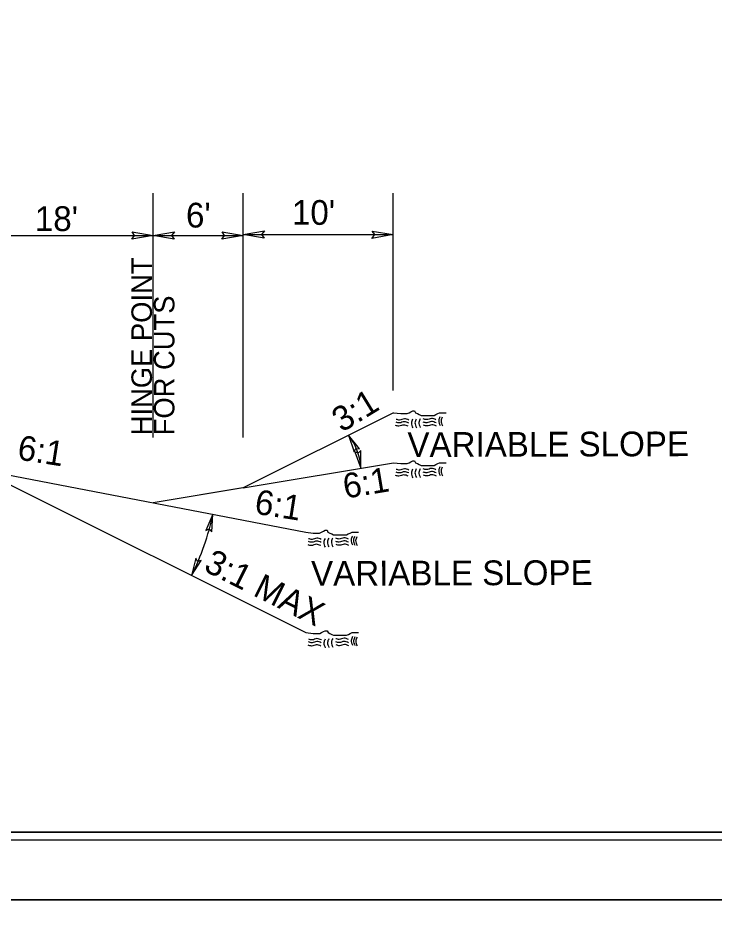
# Model space of a CAD drawing. Extents: x 2241081 to 2251104, y 658534 to 663427.
# Drawn here: x 2248675.9 to 2248908, y 659619.3 to 659923.1 of the extents above; entities that cross this region are included whole.
import ezdxf

# ---------------------------------------------------------------- set-up
doc = ezdxf.new("R2010")
doc.units = 0
for name, color, linetype in [('Old_Level_1', 7, 'Continuous'), ('Old_Level_2', 7, 'Continuous'), ('Prop Dimension', 7, 'Continuous'), ('Prop Dimension Text', 7, 'Continuous'), ('Prop PHM Text', 7, 'Continuous'), ('Sheet Cutting Line CELL', 7, 'Continuous'), ('Sheet Plan CELL', 7, 'Continuous'), ('Sheet Plot Border Inside CELL', 7, 'Continuous'), ('Sheet Plot Border Outside CELL', 7, 'Continuous'), ('Typical Hinge Slope Interstate CELL', 7, 'Continuous'), ('Typical Terminator CELL', 7, 'Continuous')]:
    doc.layers.add(name, color=color, linetype=linetype)

msp = doc.modelspace()

# ---------------------------------------------------------------- linework, layer by layer
at = {"layer": 'Old_Level_1'}
for p, q in [((2248800.89, 659791.62), (2248750.89, 659766.62)), ((2248662.87, 659772.79), (2248771.71, 659751.84)), ((2248750.89, 659766.62), (2248800.89, 659774.96)), ((2248750.89, 659766.62), (2248728.89, 659762.95))]:
    msp.add_line(p, q, dxfattribs=at)
for points in [[(2248800.89, 659791.62), (2248803.35, 659791.32), (2248803.97, 659791.32), (2248804.9, 659791.32), (2248805.51, 659791.32), (2248806.13, 659791.62), (2248806.74, 659791.93), (2248807.36, 659792.24), (2248807.98, 659792.24), (2248808.28, 659791.62), (2248808.9, 659791.32), (2248809.52, 659791.01), (2248810.13, 659790.7), (2248810.75, 659790.7), (2248811.37, 659790.7), (2248811.98, 659790.7), (2248812.6, 659790.7), (2248813.21, 659790.7), (2248813.83, 659790.7), (2248814.45, 659790.7), (2248815.06, 659791.01), (2248815.68, 659791.32), (2248816.29, 659791.62), (2248817.22, 659791.62), (2248817.84, 659791.62), (2248818.45, 659791.62)], [(2248800.89, 659774.96), (2248803.35, 659774.65), (2248803.97, 659774.65), (2248804.9, 659774.65), (2248805.51, 659774.65), (2248806.13, 659774.96), (2248806.74, 659775.27), (2248807.36, 659775.58), (2248807.98, 659775.58), (2248808.28, 659774.96), (2248808.9, 659774.65), (2248809.52, 659774.34), (2248810.13, 659774.03), (2248810.75, 659774.03), (2248811.37, 659774.03), (2248811.98, 659774.03), (2248812.6, 659774.03), (2248813.21, 659774.03), (2248813.83, 659774.03), (2248814.45, 659774.03), (2248815.06, 659774.34), (2248815.68, 659774.65), (2248816.29, 659774.96), (2248817.22, 659774.96), (2248817.84, 659774.96), (2248818.45, 659774.96)], [(2248771.71, 659751.84), (2248774.17, 659751.53), (2248774.79, 659751.53), (2248775.72, 659751.53), (2248776.33, 659751.53), (2248776.95, 659751.84), (2248777.56, 659752.15), (2248778.18, 659752.46), (2248778.8, 659752.46), (2248779.11, 659751.84), (2248779.72, 659751.53), (2248780.34, 659751.22), (2248780.95, 659750.92), (2248781.57, 659750.92), (2248782.19, 659750.92), (2248782.8, 659750.92), (2248783.42, 659750.92), (2248784.03, 659750.92), (2248784.65, 659750.92), (2248785.27, 659750.92), (2248785.88, 659751.22), (2248786.5, 659751.53), (2248787.12, 659751.84), (2248788.04, 659751.84), (2248788.66, 659751.84), (2248789.27, 659751.84)], [(2248771.75, 659718.35), (2248774.21, 659718.04), (2248774.83, 659718.04), (2248775.75, 659718.04), (2248776.37, 659718.04), (2248776.99, 659718.35), (2248777.6, 659718.66), (2248778.22, 659718.97), (2248778.83, 659718.97), (2248779.14, 659718.35), (2248779.76, 659718.04), (2248780.38, 659717.74), (2248780.99, 659717.43), (2248781.61, 659717.43), (2248782.22, 659717.43), (2248782.84, 659717.43), (2248783.46, 659717.43), (2248784.07, 659717.43), (2248784.69, 659717.43), (2248785.31, 659717.43), (2248785.92, 659717.74), (2248786.54, 659718.04), (2248787.15, 659718.35), (2248788.08, 659718.35), (2248788.69, 659718.35), (2248789.31, 659718.35)]]:
    msp.add_lwpolyline(points, dxfattribs=at)
for points in [[(2248806.02, 659788.2), (2248804.51, 659788.64), (2248802.93, 659788.23), (2248801.78, 659788.48)], [(2248806.02, 659788.2), (2248804.51, 659788.64), (2248802.93, 659788.23), (2248801.78, 659788.48)], [(2248806.06, 659789.15), (2248804.55, 659789.58), (2248802.97, 659789.17), (2248801.82, 659789.42)], [(2248806.06, 659789.15), (2248804.55, 659789.58), (2248802.97, 659789.17), (2248801.82, 659789.42)], [(2248807.31, 659789.43), (2248806.88, 659788.19), (2248807.34, 659786.55)], [(2248807.31, 659789.43), (2248806.88, 659788.19), (2248807.34, 659786.55)], [(2248808.52, 659789.54), (2248808.1, 659788.3), (2248808.55, 659786.65)], [(2248808.52, 659789.54), (2248808.1, 659788.3), (2248808.55, 659786.65)], [(2248809.83, 659789.64), (2248809.41, 659788.4), (2248809.86, 659786.76)], [(2248809.83, 659789.64), (2248809.41, 659788.4), (2248809.86, 659786.76)], [(2248815.09, 659789.29), (2248813.59, 659789.72), (2248811.99, 659789.32), (2248810.85, 659789.57)], [(2248815.09, 659789.29), (2248813.59, 659789.72), (2248811.99, 659789.32), (2248810.85, 659789.57)], [(2248815.1, 659788.24), (2248813.59, 659788.67), (2248812.01, 659788.26), (2248810.86, 659788.52)], [(2248815.1, 659788.24), (2248813.59, 659788.67), (2248812.01, 659788.26), (2248810.86, 659788.52)], [(2248816.42, 659790.26), (2248815.99, 659789.01), (2248816.45, 659787.37)], [(2248816.42, 659790.26), (2248815.99, 659789.01), (2248816.45, 659787.37)], [(2248817.2, 659790.18), (2248816.78, 659788.93), (2248817.24, 659787.28)], [(2248817.2, 659790.18), (2248816.78, 659788.93), (2248817.24, 659787.28)], [(2248805.87, 659787.11), (2248804.37, 659787.54), (2248802.77, 659787.14), (2248801.63, 659787.39)], [(2248805.87, 659787.11), (2248804.37, 659787.54), (2248802.77, 659787.14), (2248801.63, 659787.39)], [(2248815.22, 659787.19), (2248813.71, 659787.61), (2248812.12, 659787.21), (2248810.97, 659787.47)], [(2248815.22, 659787.19), (2248813.71, 659787.61), (2248812.12, 659787.21), (2248810.97, 659787.47)], [(2248806.06, 659772.48), (2248804.55, 659772.91), (2248802.97, 659772.51), (2248801.82, 659772.76)], [(2248806.06, 659772.48), (2248804.55, 659772.91), (2248802.97, 659772.51), (2248801.82, 659772.76)], [(2248807.31, 659772.77), (2248806.88, 659771.52), (2248807.34, 659769.88)], [(2248807.31, 659772.77), (2248806.88, 659771.52), (2248807.34, 659769.88)], [(2248808.52, 659772.88), (2248808.1, 659771.63), (2248808.55, 659769.99)], [(2248808.52, 659772.88), (2248808.1, 659771.63), (2248808.55, 659769.99)], [(2248809.83, 659772.98), (2248809.41, 659771.74), (2248809.86, 659770.09)], [(2248809.83, 659772.98), (2248809.41, 659771.74), (2248809.86, 659770.09)], [(2248815.09, 659772.62), (2248813.59, 659773.06), (2248811.99, 659772.65), (2248810.85, 659772.91)], [(2248815.09, 659772.62), (2248813.59, 659773.06), (2248811.99, 659772.65), (2248810.85, 659772.91)], [(2248816.42, 659773.59), (2248815.99, 659772.35), (2248816.45, 659770.71)], [(2248816.42, 659773.59), (2248815.99, 659772.35), (2248816.45, 659770.71)], [(2248817.2, 659773.51), (2248816.78, 659772.27), (2248817.24, 659770.62)], [(2248817.2, 659773.51), (2248816.78, 659772.27), (2248817.24, 659770.62)], [(2248805.87, 659770.45), (2248804.37, 659770.88), (2248802.77, 659770.47), (2248801.63, 659770.73)], [(2248805.87, 659770.45), (2248804.37, 659770.88), (2248802.77, 659770.47), (2248801.63, 659770.73)], [(2248806.02, 659771.54), (2248804.51, 659771.97), (2248802.93, 659771.56), (2248801.78, 659771.82)], [(2248806.02, 659771.54), (2248804.51, 659771.97), (2248802.93, 659771.56), (2248801.78, 659771.82)], [(2248815.1, 659771.58), (2248813.59, 659772), (2248812.01, 659771.6), (2248810.86, 659771.86)], [(2248815.1, 659771.58), (2248813.59, 659772), (2248812.01, 659771.6), (2248810.86, 659771.86)], [(2248815.22, 659770.52), (2248813.71, 659770.95), (2248812.12, 659770.55), (2248810.97, 659770.8)], [(2248815.22, 659770.52), (2248813.71, 659770.95), (2248812.12, 659770.55), (2248810.97, 659770.8)]]:
    msp.add_spline(points, degree=3, dxfattribs=at)
at = {"layer": 'Old_Level_2'}
for points in [[(2248776.84, 659748.42), (2248775.34, 659748.86), (2248773.75, 659748.44), (2248772.6, 659748.7)], [(2248776.84, 659748.42), (2248775.34, 659748.86), (2248773.75, 659748.44), (2248772.6, 659748.7)], [(2248776.88, 659749.37), (2248775.38, 659749.79), (2248773.79, 659749.39), (2248772.64, 659749.64)], [(2248776.88, 659749.37), (2248775.38, 659749.79), (2248773.79, 659749.39), (2248772.64, 659749.64)], [(2248778.13, 659749.65), (2248777.7, 659748.41), (2248778.16, 659746.76)], [(2248778.13, 659749.65), (2248777.7, 659748.41), (2248778.16, 659746.76)], [(2248779.34, 659749.76), (2248778.92, 659748.52), (2248779.37, 659746.87)], [(2248779.34, 659749.76), (2248778.92, 659748.52), (2248779.37, 659746.87)], [(2248780.65, 659749.86), (2248780.23, 659748.62), (2248780.68, 659746.97)], [(2248780.65, 659749.86), (2248780.23, 659748.62), (2248780.68, 659746.97)], [(2248785.91, 659749.51), (2248784.41, 659749.94), (2248782.82, 659749.53), (2248781.67, 659749.79)], [(2248785.91, 659749.51), (2248784.41, 659749.94), (2248782.82, 659749.53), (2248781.67, 659749.79)], [(2248785.92, 659748.46), (2248784.41, 659748.89), (2248782.83, 659748.48), (2248781.68, 659748.74)], [(2248785.92, 659748.46), (2248784.41, 659748.89), (2248782.83, 659748.48), (2248781.68, 659748.74)], [(2248787.24, 659750.48), (2248786.81, 659749.23), (2248787.27, 659747.59)], [(2248787.24, 659750.48), (2248786.81, 659749.23), (2248787.27, 659747.59)], [(2248788.02, 659750.39), (2248787.6, 659749.15), (2248788.06, 659747.5)], [(2248788.02, 659750.39), (2248787.6, 659749.15), (2248788.06, 659747.5)], [(2248788.75, 659750.25), (2248788.33, 659749.01), (2248788.78, 659747.36)], [(2248788.75, 659750.25), (2248788.33, 659749.01), (2248788.78, 659747.36)], [(2248776.69, 659747.33), (2248775.19, 659747.76), (2248773.59, 659747.35), (2248772.45, 659747.61)], [(2248786.04, 659747.4), (2248784.53, 659747.83), (2248782.94, 659747.43), (2248781.79, 659747.69)], [(2248786.04, 659747.4), (2248784.53, 659747.83), (2248782.94, 659747.43), (2248781.79, 659747.69)], [(2248776.88, 659714.93), (2248775.37, 659715.37), (2248773.79, 659714.96), (2248772.64, 659715.21)], [(2248776.88, 659714.93), (2248775.37, 659715.37), (2248773.79, 659714.96), (2248772.64, 659715.21)], [(2248776.92, 659715.88), (2248775.41, 659716.31), (2248773.83, 659715.9), (2248772.68, 659716.15)], [(2248776.92, 659715.88), (2248775.41, 659716.31), (2248773.83, 659715.9), (2248772.68, 659716.15)], [(2248778.16, 659716.16), (2248777.74, 659714.92), (2248778.2, 659713.28)], [(2248778.16, 659716.16), (2248777.74, 659714.92), (2248778.2, 659713.28)], [(2248779.38, 659716.27), (2248778.96, 659715.03), (2248779.41, 659713.38)], [(2248779.38, 659716.27), (2248778.96, 659715.03), (2248779.41, 659713.38)], [(2248780.69, 659716.37), (2248780.27, 659715.13), (2248780.72, 659713.48)], [(2248780.69, 659716.37), (2248780.27, 659715.13), (2248780.72, 659713.48)], [(2248785.95, 659716.02), (2248784.45, 659716.45), (2248782.85, 659716.05), (2248781.71, 659716.3)], [(2248785.95, 659716.02), (2248784.45, 659716.45), (2248782.85, 659716.05), (2248781.71, 659716.3)], [(2248785.96, 659714.97), (2248784.45, 659715.4), (2248782.87, 659714.99), (2248781.72, 659715.25)], [(2248785.96, 659714.97), (2248784.45, 659715.4), (2248782.87, 659714.99), (2248781.72, 659715.25)], [(2248787.28, 659716.99), (2248786.85, 659715.74), (2248787.31, 659714.1)], [(2248787.28, 659716.99), (2248786.85, 659715.74), (2248787.31, 659714.1)], [(2248788.06, 659716.91), (2248787.64, 659715.66), (2248788.09, 659714.01)], [(2248788.06, 659716.91), (2248787.64, 659715.66), (2248788.09, 659714.01)], [(2248788.79, 659716.76), (2248788.36, 659715.52), (2248788.82, 659713.87)], [(2248788.79, 659716.76), (2248788.36, 659715.52), (2248788.82, 659713.87)], [(2248776.73, 659713.84), (2248775.22, 659714.27), (2248773.63, 659713.86), (2248772.49, 659714.12)], [(2248786.07, 659713.91), (2248784.57, 659714.34), (2248782.97, 659713.94), (2248781.83, 659714.2)], [(2248786.07, 659713.91), (2248784.57, 659714.34), (2248782.97, 659713.94), (2248781.83, 659714.2)]]:
    msp.add_spline(points, degree=3, dxfattribs=at)
at = {"layer": 'Prop Dimension'}
for centre, radius, start, end in [((2248770.95, 659772.29), 19.12, 2.5693, 38.3323), ((2248661.39, 659774.2), 81.05, 333.0098, 348.3211)]:
    msp.add_arc(centre, radius, start, end, dxfattribs=at)
at = {"layer": 'Prop Dimension Text'}
for p, q in [((2248720.84, 659783.34), (2248720.84, 659864.81)), ((2248750.84, 659783.34), (2248750.84, 659864.81)), ((2248800.84, 659799.08), (2248800.84, 659864.81)), ((2248662.83, 659850.74), (2248720.84, 659850.74)), ((2248720.84, 659850.74), (2248750.84, 659850.74)), ((2248750.84, 659851.12), (2248750.84, 659851.12)), ((2248750.84, 659851), (2248800.84, 659851)), ((2248800.84, 659851.12), (2248800.84, 659851.12))]:
    msp.add_line(p, q, dxfattribs=at)
at = {"layer": 'Sheet Cutting Line CELL'}
for p, q in [((2247635.51, 659629.27), (2249319.01, 659629.26)), ((2249319.01, 659629.26), (2247635.51, 659629.27))]:
    msp.add_line(p, q, dxfattribs=at)
at = {"layer": 'Sheet Plan CELL'}
for points in [[(2247801.99, 659651.78), (2247801.97, 660701.75), (2249101.96, 660701.79), (2249101.97, 660551.73), (2249302.01, 660551.71), (2249302.01, 659651.78)], [(2249302.03, 660701.78), (2247801.99, 660701.78), (2247801.99, 659651.78), (2249302.01, 659651.78)]]:
    msp.add_lwpolyline(points, close=True, dxfattribs=at)
at = {"layer": 'Sheet Plot Border Inside CELL'}
msp.add_lwpolyline([(2247648.51, 659649.27), (2249314.49, 659649.28), (2249314.51, 660704.26), (2247648.51, 660704.27)], close=True, dxfattribs=at)
at = {"layer": 'Sheet Plot Border Outside CELL'}
for points in [[(2247635.51, 659629.27), (2249319.01, 659629.26), (2249319.01, 660724.26), (2247635.51, 660724.27)], [(2247635.5, 658534.27), (2249319, 658534.26), (2249319.01, 659629.26), (2247635.51, 659629.27)]]:
    msp.add_lwpolyline(points, close=True, dxfattribs=at)
at = {"layer": 'Typical Hinge Slope Interstate CELL'}
for p, q in [((2248662.87, 659772.79), (2248771.75, 659718.35)), ((2248751.39, 659766.7), (2248720.89, 659761.62))]:
    msp.add_line(p, q, dxfattribs=at)
at = {"layer": 'Typical Terminator CELL'}
for points in [[(2248713.81, 659851.95), (2248720.84, 659850.74), (2248713.77, 659849.49), (2248714.67, 659850.74)], [(2248727.87, 659849.53), (2248720.84, 659850.74), (2248727.91, 659851.99), (2248727.01, 659850.74)], [(2248743.81, 659851.95), (2248750.84, 659850.74), (2248743.77, 659849.49), (2248744.67, 659850.74)], [(2248757.87, 659849.79), (2248750.84, 659851), (2248757.91, 659852.25), (2248757.01, 659851)], [(2248793.81, 659852.21), (2248800.84, 659851), (2248793.77, 659849.75), (2248794.67, 659851)], [(2248789.61, 659779.58), (2248785.95, 659784.15), (2248787.86, 659778.58), (2248788.4, 659779.72)], [(2248788.05, 659778.65), (2248790.05, 659773.15), (2248790.03, 659779.04), (2248789.16, 659778.13)], [(2248740.37, 659751.96), (2248740.76, 659757.8), (2248738.4, 659752.4), (2248739.57, 659752.88)], [(2248735.02, 659743.1), (2248733.61, 659737.42), (2248736.88, 659742.32), (2248735.65, 659742.05)]]:
    msp.add_lwpolyline(points, close=True, dxfattribs=at)

# ---------------------------------------------------------------- texts
at = {"layer": 'Prop Dimension Text'}
for s, rotation, p in [("6'", 359.9999, (2248731.8, 659853.38)), ("10'", 359.9999, (2248767.11, 659854.27)), ("18'", 359.9999, (2248681.44, 659852.21)), ('6:1', 351.1342, (2248675.3, 659776.1)), ('6:1', 351.1342, (2248754.34, 659758.02))]:
    msp.add_text(s, height=8.25, rotation=rotation, dxfattribs=at).set_placement(p)
at = {"layer": 'Prop PHM Text'}
for s, height, p in [('HINGE POINT', 6.8193, (2248720.43, 659784.1)), ('FOR CUTS', 6.819, (2248727.94, 659784.1))]:
    msp.add_text(s, height=height, rotation=89.9999, dxfattribs=at).set_placement(p)
at = {"layer": 'Typical Hinge Slope Interstate CELL'}
for s, rotation, p in [('3:1', 31.5585, (2248783.72, 659784.9)), ('VARIABLE SLOPE', 0.1842, (2248805.6, 659776.86)), ('6:1', 9.4623, (2248784.83, 659762.97)), ('3:1 MAX', 333.4356, (2248737.31, 659739.13)), ('VARIABLE SLOPE', 0.1842, (2248773.48, 659733.94))]:
    msp.add_text(s, height=8.25, rotation=rotation, dxfattribs=at).set_placement(p)

doc.saveas('drawing.dxf')
